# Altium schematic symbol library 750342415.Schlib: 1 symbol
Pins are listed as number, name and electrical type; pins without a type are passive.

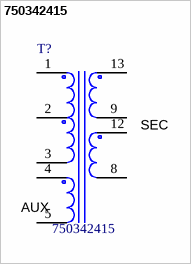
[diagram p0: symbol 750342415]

## 750342415
designator T?
TRANSFOERMER, 856uH, +/-10%, TH, 14-PIN; Manufacturer: WURTH ELEKTRONIK; CompType: TRANSFORMER; SymbolCreator: x0199378
pins: 1, 2, 3, 4, 5, 8, 9, 12, 13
